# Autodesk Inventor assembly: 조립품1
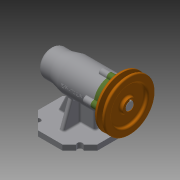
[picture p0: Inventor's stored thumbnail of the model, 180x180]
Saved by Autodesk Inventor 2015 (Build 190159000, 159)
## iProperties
Created: 2019-12
Part Number: 조립품1
Document SubType Name: Assembly
Designer: CAD-08
Author: CAD-08
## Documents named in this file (12)
- C:\Users\CAD-08\Desktop\491204V1056\조립품1.iam
- C:\Users\CAD-08\Desktop\491204V1056\Ű 5 x 5 x 16.ipt
- C:\Users\CAD-08\Desktop\491204V1056\V벨트풀리.ipt
- C:\Users\CAD-08\Desktop\491204V1056\멈춤나사 M3.ipt
- C:\Users\CAD-08\Desktop\491204V1056\베어링 6004.ipt
- C:\Users\CAD-08\Desktop\491204V1056\베어링 51202.ipt
- C:\Users\CAD-08\Desktop\491204V1056\본체.ipt
- C:\Users\CAD-08\Desktop\491204V1056\볼트 M4.ipt
- C:\Users\CAD-08\Desktop\491204V1056\어댑터슬리브.ipt
- C:\Users\CAD-08\Desktop\491204V1056\오일 실.ipt
- C:\Users\CAD-08\Desktop\491204V1056\축.ipt
- C:\Users\CAD-08\Desktop\491204V1056\커버.ipt
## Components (2 placed, 2 different names)
1. Ű 5 x 5 x 16:1
2. V벨트풀리:1 — 플러쉬:1
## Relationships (1: Flush 1)
- 플러쉬:1 [Flush]: V벨트풀리:1
